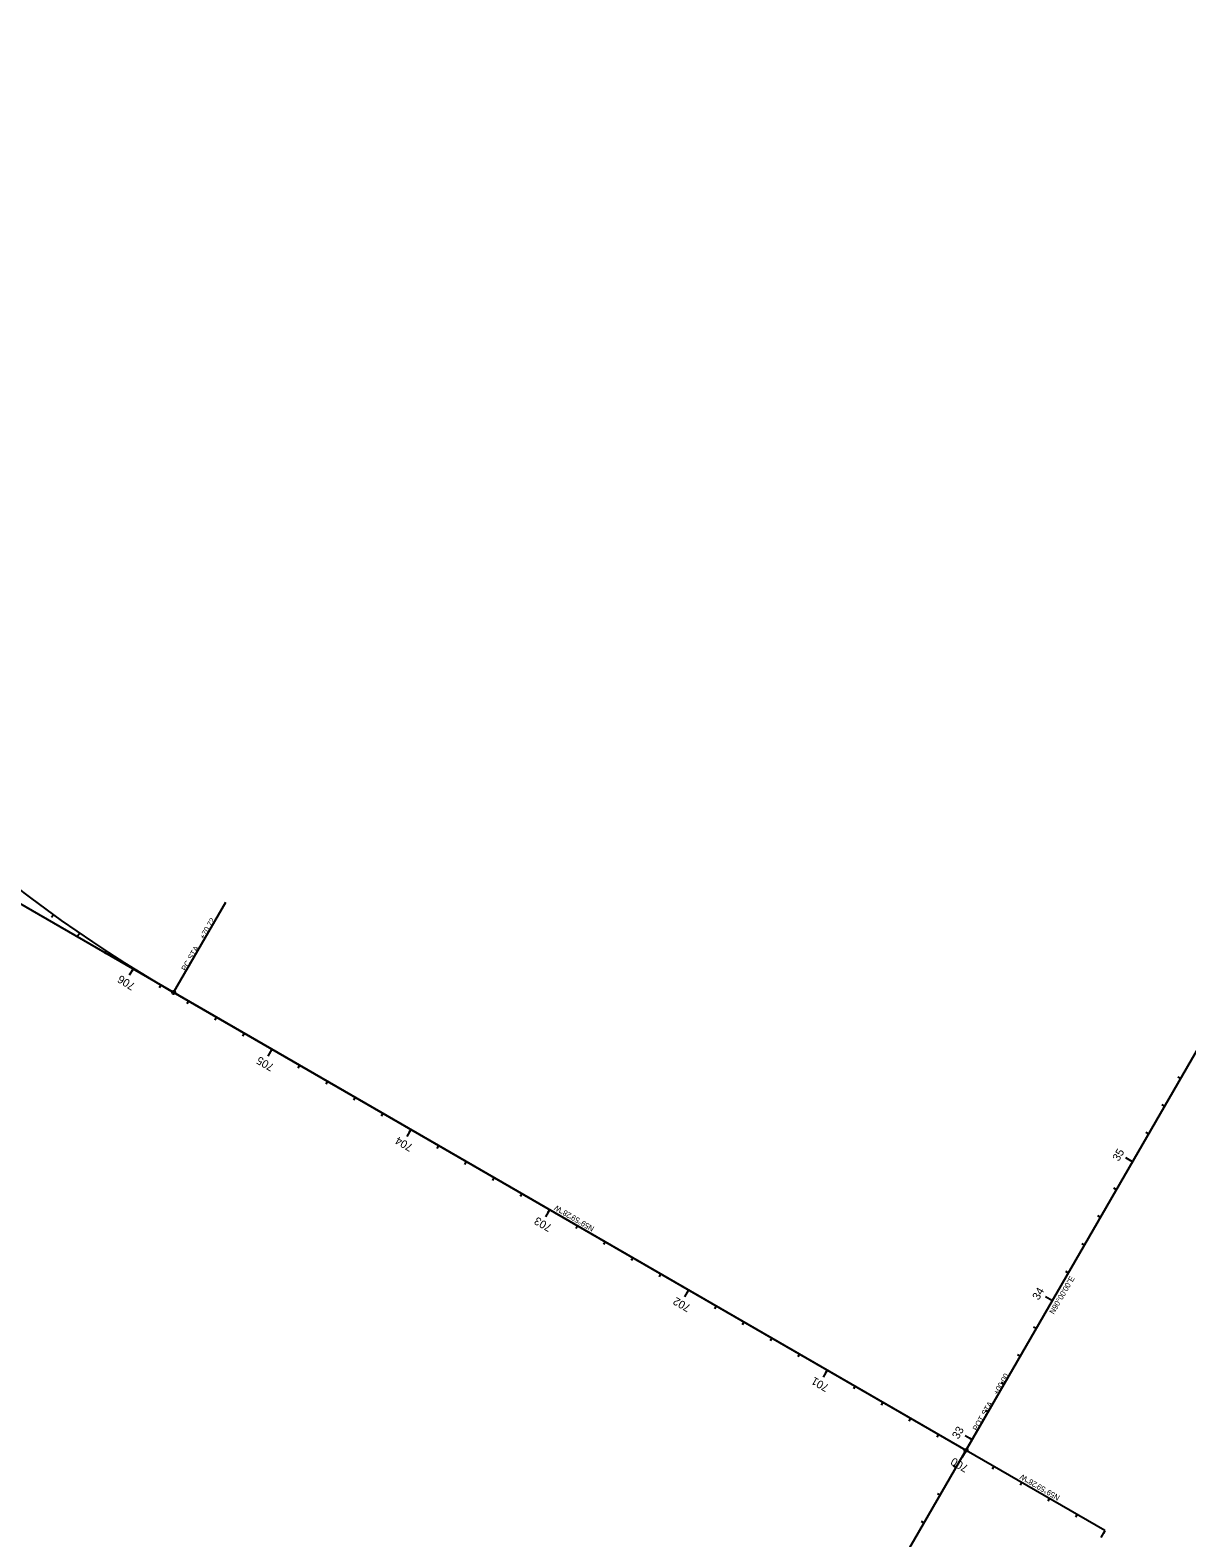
# Model space of a CAD drawing. Extents: x 2003883 to 2007688, y 399149 to 412300.
# Drawn here: x 2006250 to 2006971, y 402588 to 403528 of the extents above; entities that cross this region are included whole.
import ezdxf

# ---------------------------------------------------------------- set-up
doc = ezdxf.new("R2010")
doc.units = 0
for name, color, linetype in [('BaselineSurvey', 7, 'Continuous'), ('CLConst_dp', 7, 'Continuous'), ('ConstLines', 7, 'Continuous'), ('TextAlgnCardinalPnt', 7, 'Continuous'), ('TextAlgnStation100', 7, 'Continuous'), ('TextAlgnStation1000', 7, 'Continuous'), ('TextAlgnStation500', 7, 'Continuous'), ('TextAlgnStation5000', 7, 'Continuous'), ('TextAlgnTangent', 7, 'Continuous'), ('TextAlgnTicks100', 7, 'Continuous'), ('TextAlgnTicks1000', 7, 'Continuous'), ('TextAlgnTicks500', 7, 'Continuous'), ('TextAlgnTicks5000', 7, 'Continuous')]:
    doc.layers.add(name, color=color, linetype=linetype)

msp = doc.modelspace()

# ---------------------------------------------------------------- linework, layer by layer
at = {"layer": 'BaselineSurvey'}
msp.add_lwpolyline([(2006095.1, 401364.22), (2006751.44, 402500.64), (2007687.69, 404121.69)], dxfattribs=at)
at = {"layer": 'CLConst_dp'}
for p, q in [((2006833.64, 402642.95), (2006339.42, 402928.39)), ((2006920.23, 402592.94), (2006833.64, 402642.95))]:
    msp.add_line(p, q, dxfattribs=at)
msp.add_arc((2006780.04, 403691.29), 881, 190.93889, 239.99111, dxfattribs=at)
at = {"layer": 'ConstLines'}
for q in [(2005101.74, 403643.22), (2006339.42, 402928.39)]:
    msp.add_line((2006833.64, 402642.95), q, dxfattribs=at)
msp.add_arc((2006780.04, 403691.29), 881, 190.93889, 239.99111, dxfattribs=at)
at = {"layer": 'TextAlgnCardinalPnt'}
for p, q in [((2006339.42, 402928.39), (2006371.93, 402984.68)), ((2006833.64, 402642.95), (2006866.14, 402699.24))]:
    msp.add_line(p, q, dxfattribs=at)
for centre in [(2006339.42, 402928.39), (2006833.64, 402642.95)]:
    msp.add_circle(centre, 1, dxfattribs=at)
at = {"layer": 'TextAlgnTicks100'}
for p, q in [((2006264.5, 402976.88), (2006263.33, 402975.26)), ((2006280.85, 402965.36), (2006279.72, 402963.71)), ((2006297.46, 402954.22), (2006296.36, 402952.54)), ((2006314.31, 402943.45), (2006311.67, 402939.21)), ((2006331.41, 402933.07), (2006330.39, 402931.35)), ((2006348.7, 402923.03), (2006347.7, 402921.3)), ((2006366.02, 402913.03), (2006365.02, 402911.29)), ((2006383.34, 402903.02), (2006382.34, 402901.29)), ((2006400.66, 402893.02), (2006398.16, 402888.69)), ((2006417.98, 402883.02), (2006416.98, 402881.29)), ((2006967.5, 402874.72), (2006965.76, 402875.72)), ((2006435.3, 402873.01), (2006434.3, 402871.28)), ((2006452.62, 402863.01), (2006451.62, 402861.28)), ((2006957.49, 402857.4), (2006955.76, 402858.4)), ((2006469.94, 402853.01), (2006468.94, 402851.28)), ((2006487.26, 402843.01), (2006484.76, 402838.68)), ((2006947.49, 402840.08), (2006945.76, 402841.08)), ((2006504.58, 402833), (2006503.58, 402831.27)), ((2006521.89, 402823), (2006520.89, 402821.27)), ((2006937.49, 402822.77), (2006933.16, 402825.27)), ((2006539.21, 402813), (2006538.21, 402811.27)), ((2006556.53, 402803), (2006555.53, 402801.26)), ((2006927.48, 402805.45), (2006925.75, 402806.45)), ((2006573.85, 402792.99), (2006571.35, 402788.66)), ((2006917.48, 402788.13), (2006915.75, 402789.13)), ((2006591.17, 402782.99), (2006590.17, 402781.26)), ((2006608.49, 402772.99), (2006607.49, 402771.26)), ((2006907.48, 402770.81), (2006905.75, 402771.81)), ((2006625.81, 402762.99), (2006624.81, 402761.25)), ((2006643.13, 402752.98), (2006642.13, 402751.25)), ((2006897.48, 402753.49), (2006895.74, 402754.49)), ((2006660.45, 402742.98), (2006657.95, 402738.65)), ((2006677.76, 402732.98), (2006676.76, 402731.25)), ((2006887.47, 402736.17), (2006883.14, 402738.67)), ((2006695.08, 402722.97), (2006694.08, 402721.24)), ((2006877.47, 402718.85), (2006875.74, 402719.85)), ((2006712.4, 402712.97), (2006711.4, 402711.24)), ((2006729.72, 402702.97), (2006728.72, 402701.24)), ((2006867.47, 402701.53), (2006865.74, 402702.53)), ((2006747.04, 402692.97), (2006744.54, 402688.64)), ((2006857.47, 402684.21), (2006855.73, 402685.21)), ((2006764.36, 402682.96), (2006763.36, 402681.23)), ((2006781.68, 402672.96), (2006780.68, 402671.23)), ((2006847.46, 402666.89), (2006845.73, 402667.9)), ((2006799, 402662.96), (2006798, 402661.23)), ((2006816.32, 402652.96), (2006815.32, 402651.22)), ((2006837.46, 402649.58), (2006833.13, 402652.08)), ((2006833.64, 402642.95), (2006831.13, 402638.62)), ((2006827.46, 402632.26), (2006825.73, 402633.26)), ((2006850.95, 402632.95), (2006849.95, 402631.22)), ((2006868.27, 402622.95), (2006867.27, 402621.22)), ((2006817.46, 402614.94), (2006815.72, 402615.94)), ((2006885.59, 402612.95), (2006884.59, 402611.21)), ((2006902.91, 402602.94), (2006901.91, 402601.21)), ((2006807.45, 402597.62), (2006805.72, 402598.62)), ((2006920.23, 402592.94), (2006917.73, 402588.61))]:
    msp.add_line(p, q, dxfattribs=at)
at = {"layer": 'TextAlgnTicks1000'}
for p, q in [((2006314.31, 402943.45), (2006313.26, 402941.75)), ((2006487.26, 402843.01), (2006486.26, 402841.28)), ((2006660.45, 402742.98), (2006659.45, 402741.25)), ((2006887.47, 402736.17), (2006885.74, 402737.17)), ((2006833.64, 402642.95), (2006831.13, 402638.62))]:
    msp.add_line(p, q, dxfattribs=at)
at = {"layer": 'TextAlgnTicks500'}
for p, q in [((2006314.31, 402943.45), (2006313.26, 402941.75)), ((2006400.66, 402893.02), (2006398.16, 402888.69)), ((2006487.26, 402843.01), (2006486.26, 402841.28)), ((2006937.49, 402822.77), (2006933.16, 402825.27)), ((2006573.85, 402792.99), (2006572.85, 402791.26)), ((2006660.45, 402742.98), (2006659.45, 402741.25)), ((2006887.47, 402736.17), (2006885.74, 402737.17)), ((2006747.04, 402692.97), (2006746.04, 402691.23)), ((2006837.46, 402649.58), (2006835.73, 402650.58)), ((2006833.64, 402642.95), (2006831.13, 402638.62)), ((2006920.23, 402592.94), (2006919.23, 402591.21))]:
    msp.add_line(p, q, dxfattribs=at)
at = {"layer": 'TextAlgnTicks5000'}
msp.add_line((2006833.64, 402642.95), (2006831.13, 402638.62), dxfattribs=at)

# ---------------------------------------------------------------- texts
at = {"layer": 'TextAlgnCardinalPnt'}
for s, p in [('+70.72', (2006358.4, 402961.26)), ('PC', (2006347, 402941.52)), (' STA. ', (2006350.34, 402947.3)), ('+00.00', (2006853.41, 402677.19)), (' STA. ', (2006845.34, 402663.23)), ('POT', (2006840.47, 402654.78))]:
    msp.add_text(s, height=3.48, rotation=59.99111, dxfattribs=at).set_placement(p)
at = {"layer": 'TextAlgnStation100'}
for s, rotation, p in [('706', 148.08721, (2006315.87, 402933.65)), ('705', 149.99111, (2006402.57, 402883.26)), ('704', 149.99111, (2006489.1, 402833.28)), ('35', 59.99111, (2006928.84, 402822.79)), ('703', 149.99111, (2006575.78, 402783.22)), ('34', 59.99111, (2006878.87, 402736.26)), ('702', 149.99111, (2006662.37, 402733.2)), ('701', 149.99111, (2006748.58, 402683.42)), ('33', 59.99111, (2006828.8, 402649.58)), ('700', 149.99111, (2006835.51, 402633.21))]:
    msp.add_text(s, height=4.98, rotation=rotation, dxfattribs=at).set_placement(p)
at = {"layer": 'TextAlgnStation1000'}
msp.add_text('700', height=4.98, rotation=149.99111, dxfattribs=at).set_placement((2006835.51, 402633.21))
at = {"layer": 'TextAlgnStation500'}
for s, rotation, p in [('705', 149.99111, (2006402.57, 402883.26)), ('35', 59.99111, (2006928.84, 402822.79)), ('700', 149.99111, (2006835.51, 402633.21))]:
    msp.add_text(s, height=4.98, rotation=rotation, dxfattribs=at).set_placement(p)
at = {"layer": 'TextAlgnStation5000'}
msp.add_text('700', height=4.98, rotation=149.99111, dxfattribs=at).set_placement((2006835.51, 402633.21))
at = {"layer": 'TextAlgnTangent'}
for s, rotation, p in [('N59°59\'28"W', 149.99111, (2006602.09, 402782.22)), ('N90°00\'00"E', 59.99111, (2006888.35, 402727.51)), ('N59°59\'28"W', 149.99111, (2006892.49, 402614.49))]:
    msp.add_text(s, height=3.48, rotation=rotation, dxfattribs=at).set_placement(p)

doc.saveas('drawing.dxf')
